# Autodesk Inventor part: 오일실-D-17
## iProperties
IsCustomPart: 0
Company: 한국ATC센터
Created: 2014-12
Part Number: 오일실-D-17
Material: 고무
Description: 오일-실
Document SubType Name: Modeling
Standard: KS B 2804
Designer: KYOUNG IL JANG
Standards Organization: KS
Language: ko-KR
Size Designation: D - 17 30 8
Categories: <MemberInstance><Categories><Category DisplayName="샤프트 부품" InternalName="7f7aeb1f-a693-4053-b835-cee3144e0d98" Mnemonic="SHFT"><Category DisplayName="실링" Intern
Density: 0.93 g/cm^3
Mass: 2.05797 g
Surface Area: 29.3036 cm^2
Volume: 2.21288 cm^3
Author: KYOUNG IL JANG
